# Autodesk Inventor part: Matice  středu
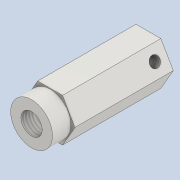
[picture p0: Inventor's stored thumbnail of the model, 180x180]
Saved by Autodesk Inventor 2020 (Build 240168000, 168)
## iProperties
Created: 2025-03
Part Number: Matice  středu
Material: Ocel
Document SubType Name: Modeling
Designer: doma
Density: 7.85 g/cm^3
Appearance: Ocel
Author: doma
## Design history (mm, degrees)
sketch "Náčrt1"
  geometry: L1 (10.104, 17.5)-(20.207, 0); L2 (20.207, 0)-(10.104, -17.5); L3 (10.104, -17.5)-(-10.104, -17.5); L4 (-10.104, -17.5)-(-20.207, 0); L5 (-20.207, 0)-(-10.104, 17.5); L6 (-10.104, 17.5)-(10.104, 17.5); 2 further points
  constraints: 12 end point, 1 coincident, 13 other
  dimensions: "d0" = 35 distance between parallel lines of L3 L6
extrude "Vysunutí1" new body sketch "Náčrt1" distance "d1" = 80; taper "d2" = 0 deg
sketch "Náčrt3"
  geometry: C1 r 17 at (0, 0); 1 further point
  constraints: 1 centre point, 1 coincident
  dimensions: "d3" = 34 diameter of C1
extrude "Vysunutí2" join sketch "Náčrt3" distance "d4" = 15; taper "d5" = 0 deg
sketch "Náčrt4"
  geometry: 2 further points
  constraints: 1 coincident
hole "Díra1" sketch "Náčrt4" at (0, 0) diameter "d6" = 17.294; stored, may be unused: countersink angle "d10" = 90 deg, drill point angle "d12" = 118 deg; dims "d7" = 45, "d8" = 4, "d9" = 2, "d11" = 55.2
sketch "Náčrt5"
  geometry: 2 further points
  dimensions: "d17" = 10 distance of point (70, -10.104) point (80, -10.104)
hole "Díra2" sketch "Náčrt5" at (70, -10.104) diameter "d18" = 8.376; stored, may be unused: countersink angle "d22" = 90 deg, drill point angle "d24" = 118 deg; dims "d19" = 20, "d20" = 4, "d21" = 2, "d23" = 27.3
node "Těleso1"
